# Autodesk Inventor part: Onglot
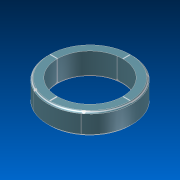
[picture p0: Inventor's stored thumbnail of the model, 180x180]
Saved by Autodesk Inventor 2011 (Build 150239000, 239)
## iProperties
Created: 2011-05
Part Number: Onglot
Document SubType Name: Modeling
Designer: 904Chiaki
Density: 1 g/cm^3
Mass: 56.6911 g
Surface Area: 159.147 cm^2
Volume: 56.6911 cm^3
Author: 904Chiaki
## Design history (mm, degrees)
sketch "Sketch1"
  geometry: C1 r 35 at (-14.18, 7.422); C2 r 45 at (-14.18, 7.422); 1 further point
  constraints: 2 centre point, 1 coincident
  dimensions: "d0" = 70 diameter of C1; "d1" = 90 diameter of C2
extrude "Extrusion1" new body sketch "Sketch1" distance "d2" = 23; taper "d3" = 0 deg
chamfer "Chamfer1" distance "d4" = 2; stored, may be unused: second distance "d5" = 2, angle "d6" = 45 deg
body "Solid1"
